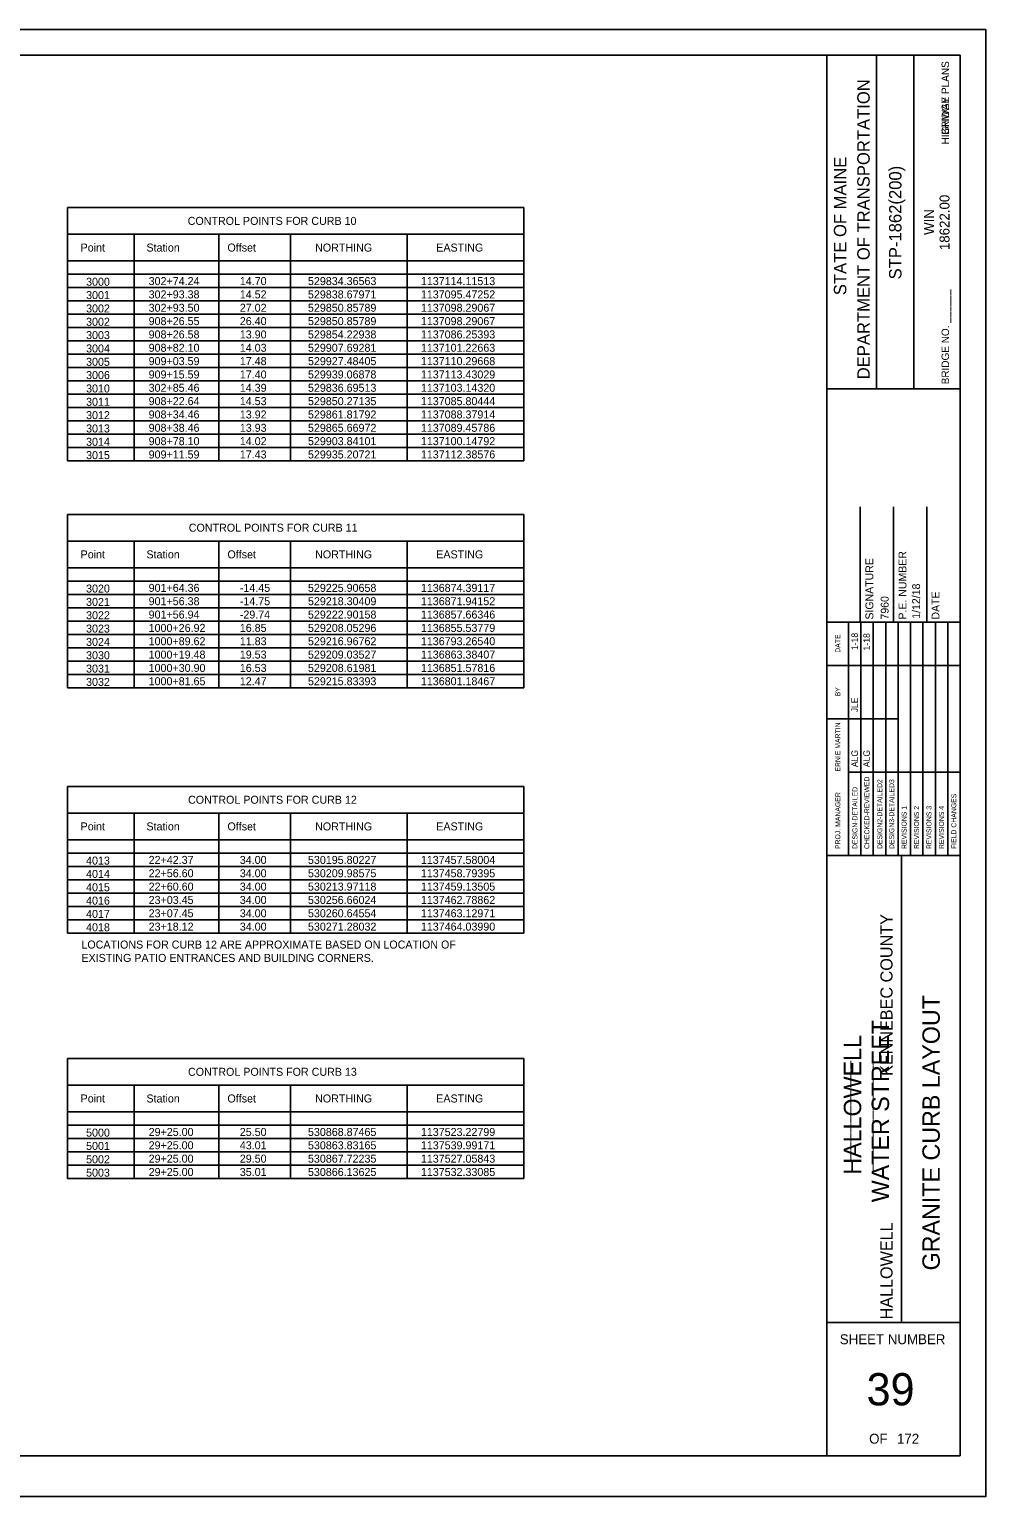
# Model space of a CAD drawing. Extents: x 0 to 850, y 0 to 550.
# Drawn here: x 491 to 850, y 0 to 550 of the extents above; entities that cross this region are included whole.
import ezdxf

# ---------------------------------------------------------------- set-up
doc = ezdxf.new("R2010")
doc.units = 0
for name, color, linetype in [('ANNOTATION', 7, 'Continuous'), ('BORDER', 7, 'Continuous'), ('BRIDGE_TITLE', 7, 'Continuous'), ('Default', 7, 'Continuous'), ('H_V CONTROLS', 7, 'Continuous'), ('HIGHWAY_TITLE', 7, 'Continuous'), ('PLOT BOUNDARY', 7, 'Continuous')]:
    doc.layers.add(name, color=color, linetype=linetype)

msp = doc.modelspace()

# ---------------------------------------------------------------- linework, layer by layer
at = {"layer": 'BORDER'}
for p, q in [((840.33, 540.24), (40.33, 540.24)), ((790.33, 15.26), (790.33, 540.26)), ((808.97, 415.23), (808.97, 540.23)), ((822.95, 415.23), (822.95, 540.23)), ((840.33, 15.26), (840.33, 540.26)), ((790.34, 415.22), (840.33, 415.22)), ((802.83, 327.76), (802.83, 371)), ((815.33, 327.76), (815.33, 371)), ((827.83, 327.76), (827.83, 371)), ((790.33, 327.76), (840.33, 327.76)), ((790.33, 240.26), (840.33, 240.26)), ((818.29, 65.26), (818.29, 240.26)), ((790.33, 65.26), (840.33, 65.26)), ((40.33, 15.24), (840.33, 15.24))]:
    msp.add_line(p, q, dxfattribs=at)
for points in [[(798.41, 311.51), (798.41, 327.76)], [(803.07, 240.27), (803.07, 327.76)], [(807.73, 327.76), (807.73, 240.27)], [(812.39, 240.27), (812.39, 327.76)], [(817.04, 240.27), (817.04, 327.76)], [(821.7, 240.27), (821.7, 327.76)], [(826.36, 240.27), (826.36, 327.76)], [(831.02, 240.27), (831.02, 327.76)], [(835.68, 240.27), (835.68, 327.76)], [(798.41, 240.27), (798.41, 324.23)], [(790.33, 311.51), (840.33, 311.51)], [(790.33, 291.51), (798.41, 291.51)], [(798.41, 291.51), (817.04, 291.51)], [(798.41, 271.51), (840.33, 271.51)]]:
    msp.add_lwpolyline(points, dxfattribs=at)
at = {"layer": 'Default'}
msp.add_lwpolyline([(40.33, 15.24), (790.33, 15.24), (790.33, 540.26), (40.33, 540.26)], close=True, dxfattribs=at)
at = {"layer": 'H_V CONTROLS'}
for p, q in [((505.47, 483.15), (676.71, 483.15)), ((505.47, 483.15), (505.47, 388.15)), ((676.71, 483.15), (676.71, 388.15)), ((505.47, 473.15), (676.71, 473.15)), ((530.51, 473.15), (530.51, 388.15)), ((562.29, 473.15), (562.29, 388.15)), ((589.21, 473.15), (589.21, 388.15)), ((632.96, 473.15), (632.96, 388.15)), ((505.47, 463.15), (676.71, 463.15)), ((505.47, 458.15), (676.71, 458.15)), ((505.47, 453.15), (676.71, 453.15)), ((505.47, 448.15), (676.71, 448.15)), ((505.47, 443.15), (676.71, 443.15)), ((505.47, 438.15), (676.71, 438.15)), ((505.47, 433.15), (676.71, 433.15)), ((505.47, 428.15), (676.71, 428.15)), ((505.47, 423.15), (676.71, 423.15)), ((505.47, 418.15), (676.71, 418.15)), ((505.47, 413.15), (676.71, 413.15)), ((505.47, 408.15), (676.71, 408.15)), ((505.47, 403.15), (676.71, 403.15)), ((505.47, 398.15), (676.71, 398.15)), ((505.47, 393.15), (676.71, 393.15)), ((505.47, 388.15), (676.71, 388.15)), ((505.47, 368.15), (676.71, 368.15)), ((505.47, 368.15), (505.47, 303.15)), ((676.71, 368.15), (676.71, 303.15)), ((505.47, 358.15), (676.71, 358.15)), ((530.51, 358.15), (530.51, 303.15)), ((562.29, 358.15), (562.29, 303.15)), ((589.21, 358.15), (589.21, 303.15)), ((632.96, 358.15), (632.96, 303.15)), ((505.47, 348.15), (676.71, 348.15)), ((505.47, 343.15), (676.71, 343.15)), ((505.47, 338.15), (676.71, 338.15)), ((505.47, 333.15), (676.71, 333.15)), ((505.47, 328.15), (676.71, 328.15)), ((505.47, 323.15), (676.71, 323.15)), ((505.47, 318.15), (676.71, 318.15)), ((505.47, 313.15), (676.71, 313.15)), ((505.47, 308.15), (676.71, 308.15)), ((505.47, 303.15), (676.71, 303.15)), ((505.47, 266.18), (676.71, 266.18)), ((505.47, 266.18), (505.47, 211.18)), ((676.71, 266.18), (676.71, 211.18)), ((505.47, 256.18), (676.71, 256.18)), ((530.51, 256.18), (530.51, 211.18)), ((562.29, 256.18), (562.29, 211.18)), ((589.21, 256.18), (589.21, 211.18)), ((632.96, 256.18), (632.96, 211.18)), ((505.47, 246.18), (676.71, 246.18)), ((505.47, 241.18), (676.71, 241.18)), ((505.47, 236.18), (676.71, 236.18)), ((505.47, 231.18), (676.71, 231.18)), ((505.47, 226.18), (676.71, 226.18)), ((505.47, 221.18), (676.71, 221.18)), ((505.47, 216.18), (676.71, 216.18)), ((505.47, 211.18), (676.71, 211.18)), ((505.47, 164.2), (676.71, 164.2)), ((505.47, 164.2), (505.47, 119.2)), ((676.71, 164.2), (676.71, 119.2)), ((505.47, 154.2), (676.71, 154.2)), ((530.51, 154.2), (530.51, 119.2)), ((562.29, 154.2), (562.29, 119.2)), ((589.21, 154.2), (589.21, 119.2)), ((632.96, 154.2), (632.96, 119.2)), ((505.47, 144.2), (676.71, 144.2)), ((505.47, 139.2), (676.71, 139.2)), ((505.47, 134.2), (676.71, 134.2)), ((505.47, 129.2), (676.71, 129.2)), ((505.47, 124.2), (676.71, 124.2)), ((505.47, 119.2), (676.71, 119.2))]:
    msp.add_line(p, q, dxfattribs=at)
at = {"layer": 'PLOT BOUNDARY'}
msp.add_lwpolyline([(-0.13, -0.05), (849.87, -0.05), (849.87, 549.95), (-0.13, 549.95)], close=True, dxfattribs=at)

# ---------------------------------------------------------------- texts
at = {"layer": 'ANNOTATION'}
for s, p in [('3000', (512.5, 453.84)), ('302+74.24', (535.96, 454.09)), ('14.70', (570.15, 454.09)), ('529834.36563', (595.71, 454.09)), ('1137114.11513', (638.05, 454.09)), ('3001', (512.5, 448.84)), ('302+93.38', (535.96, 449.09)), ('14.52', (570.15, 449.09)), ('529838.67971', (595.71, 449.09)), ('1137095.47252', (638.05, 449.09)), ('3002', (512.5, 443.84)), ('302+93.50', (535.96, 444.09)), ('27.02', (570.15, 444.09)), ('529850.85789', (595.71, 444.09)), ('1137098.29067', (638.05, 444.09)), ('3002', (512.5, 438.84)), ('908+26.55', (535.96, 439.09)), ('26.40', (570.15, 439.09)), ('529850.85789', (595.71, 439.09)), ('1137098.29067', (638.05, 439.09)), ('3003', (512.5, 433.84)), ('908+26.58', (535.96, 434.09)), ('13.90', (570.15, 434.09)), ('529854.22938', (595.71, 434.09)), ('1137086.25393', (638.05, 434.09)), ('3004', (512.5, 428.84)), ('908+82.10', (535.96, 429.09)), ('14.03', (570.15, 429.09)), ('529907.69281', (595.71, 429.09)), ('1137101.22663', (638.05, 429.09)), ('3005', (512.5, 423.84)), ('909+03.59', (535.96, 424.09)), ('17.48', (570.15, 424.09)), ('529927.48405', (595.71, 424.09)), ('1137110.29668', (638.05, 424.09)), ('3006', (512.5, 418.84)), ('909+15.59', (535.96, 419.09)), ('17.40', (570.15, 419.09)), ('529939.06878', (595.71, 419.09)), ('1137113.43029', (638.05, 419.09)), ('3010', (512.5, 413.84)), ('302+85.46', (535.96, 414.09)), ('14.39', (570.15, 414.09)), ('529836.69513', (595.71, 414.09)), ('1137103.14320', (638.05, 414.09)), ('3011', (512.5, 408.84)), ('908+22.64', (535.96, 409.09)), ('908+34.46', (535.96, 404.09)), ('14.53', (570.15, 409.09)), ('13.92', (570.15, 404.09)), ('529850.27135', (595.71, 409.09)), ('529861.81792', (595.71, 404.09)), ('1137085.80444', (638.05, 409.09)), ('1137088.37914', (638.05, 404.09)), ('3012', (512.5, 403.84)), ('3013', (512.5, 398.85)), ('908+38.46', (535.96, 399.09)), ('13.93', (570.15, 399.09)), ('529865.66972', (595.71, 399.09)), ('1137089.45786', (638.05, 399.09)), ('3014', (512.5, 393.85)), ('908+78.10', (535.96, 394.09)), ('14.02', (570.15, 394.09)), ('529903.84101', (595.71, 394.09)), ('1137100.14792', (638.05, 394.09)), ('3015', (512.5, 388.85)), ('909+11.59', (535.96, 389.1)), ('17.43', (570.15, 389.1)), ('529935.20721', (595.71, 389.1)), ('1137112.38576', (638.05, 389.1)), ('3020', (512.5, 338.84)), ('901+64.36', (535.96, 339.09)), ('-14.45', (570.15, 339.09)), ('529225.90658', (595.71, 339.09)), ('1136874.39117', (638.05, 339.09)), ('3021', (512.5, 333.84)), ('901+56.38', (535.96, 334.09)), ('-14.75', (570.15, 334.09)), ('529218.30409', (595.71, 334.09)), ('1136871.94152', (638.05, 334.09)), ('3022', (512.5, 328.84)), ('901+56.94', (535.96, 329.09)), ('-29.74', (570.15, 329.09)), ('529222.90158', (595.71, 329.09)), ('1136857.66346', (638.05, 329.09)), ('3023', (512.5, 323.84)), ('1000+26.92', (535.96, 324.09)), ('16.85', (570.15, 324.09)), ('529208.05296', (595.71, 324.09)), ('1136855.53779', (638.05, 324.09)), ('3024', (512.5, 318.84)), ('1000+89.62', (535.96, 319.09)), ('11.83', (570.15, 319.09)), ('529216.96762', (595.71, 319.09)), ('1136793.26540', (638.05, 319.09)), ('3030', (512.5, 313.84)), ('1000+19.48', (535.96, 314.09)), ('19.53', (570.15, 314.09)), ('529209.03527', (595.71, 314.09)), ('1136863.38407', (638.05, 314.09)), ('3031', (512.5, 308.84)), ('1000+30.90', (535.96, 309.09)), ('16.53', (570.15, 309.09)), ('529208.61981', (595.71, 309.09)), ('1136851.57816', (638.05, 309.09)), ('3032', (512.5, 303.84)), ('1000+81.65', (535.96, 304.09)), ('12.47', (570.15, 304.09)), ('529215.83393', (595.71, 304.09)), ('1136801.18467', (638.05, 304.09)), ('4013', (512.5, 236.87)), ('22+42.37', (535.96, 237.12)), ('34.00', (570.15, 237.12)), ('530195.80227', (595.71, 237.12)), ('1137457.58004', (638.05, 237.12)), ('4014', (512.5, 231.87)), ('22+56.60', (535.96, 232.12)), ('34.00', (570.15, 232.12)), ('530209.98575', (595.71, 232.12)), ('1137458.79395', (638.05, 232.12)), ('4015', (512.5, 226.87)), ('22+60.60', (535.96, 227.12)), ('34.00', (570.15, 227.12)), ('530213.97118', (595.71, 227.12)), ('1137459.13505', (638.05, 227.12)), ('4016', (512.5, 221.87)), ('23+03.45', (535.96, 222.12)), ('23+07.45', (535.96, 217.12)), ('34.00', (570.15, 222.12)), ('34.00', (570.15, 217.12)), ('530256.66024', (595.71, 222.12)), ('530260.64554', (595.71, 217.12)), ('1137462.78862', (638.05, 222.12)), ('1137463.12971', (638.05, 217.12)), ('4017', (512.5, 216.87)), ('4018', (512.5, 211.87)), ('23+18.12', (535.96, 212.12)), ('34.00', (570.15, 212.12)), ('530271.28032', (595.71, 212.12)), ('1137464.03990', (638.05, 212.12)), ('LOCATIONS FOR CURB 12 ARE APPROXIMATE BASED ON LOCATION OF ', (510.74, 205.39)), ('EXISTING PATIO ENTRANCES AND BUILDING CORNERS.', (510.74, 200.39)), ('5000', (512.5, 134.9)), ('29+25.00', (535.96, 135.15)), ('25.50', (570.15, 135.15)), ('530868.87465', (595.71, 135.15)), ('1137523.22799', (638.05, 135.15)), ('5001', (512.5, 129.9)), ('29+25.00', (535.96, 130.15)), ('43.01', (570.15, 130.15)), ('530863.83165', (595.71, 130.15)), ('1137539.99171', (638.05, 130.15)), ('5002', (512.5, 124.9)), ('29+25.00', (535.96, 125.15)), ('29.50', (570.15, 125.15)), ('530867.72235', (595.71, 125.15)), ('1137527.05843', (638.05, 125.15)), ('5003', (512.5, 119.9)), ('29+25.00', (535.96, 120.15)), ('35.01', (570.15, 120.15)), ('530866.13625', (595.71, 120.15)), ('1137532.33085', (638.05, 120.15))]:
    msp.add_text(s, height=3, rotation=360, dxfattribs=at).set_placement(p)
at = {"layer": 'BORDER'}
for s, height, p in [('DEPARTMENT OF TRANSPORTATION', 4.6588, (806.37, 418.77)), ('STATE OF MAINE', 4.6588, (797.61, 450.3)), ('STP-1862(200)', 4.6588, (818.29, 456.21)), ('18622.00', 3.726, (836.31, 467.18)), ('WIN', 3.726, (830.52, 472.89)), ('P.E. NUMBER', 2.9528, (820.14, 328.72)), ('SIGNATURE', 2.953, (807.73, 328.72)), ('1/12/18', 2.953, (825.27, 329.02)), ('7960', 2.953, (813.47, 328.72)), ('DATE', 2.953, (832.54, 328.72)), ('DATE', 1.857, (795.35, 316.29)), ('1-18', 2.423, (801.95, 317.25)), ('1-18', 2.423, (806.42, 317.14)), ('BY', 1.857, (795.35, 299.93)), ('JLE', 2.423, (801.95, 293.93)), ('ERNIE MARTIN', 1.8637, (795.35, 271.72)), ('ALG', 2.423, (801.95, 273.38)), ('ALG', 2.423, (806.42, 273.38)), ('DESIGN-DETAILED', 1.8637, (801.76, 242.7)), ('CHECKED-REVIEWED', 1.8637, (806.24, 242.7)), ('DESIGN2-DETAILED2', 1.8637, (811.08, 242.7)), ('DESIGN3-DETAILED3', 1.8637, (815.55, 242.7)), ('PROJ. MANAGER', 1.8637, (795.35, 242.7)), ('FIELD CHANGES', 1.8637, (838.85, 242.7)), ('REVISIONS 1', 1.8637, (820.21, 242.7)), ('REVISIONS 2', 1.8637, (824.87, 242.7)), ('REVISIONS 3', 1.8637, (829.53, 242.7)), ('REVISIONS 4', 1.8637, (834.19, 242.7)), ('GRANITE CURB LAYOUT', 6.5214, (832.66, 84.75))]:
    msp.add_text(s, height=height, rotation=90, dxfattribs=at).set_placement(p)
for s, height, p in [('SHEET NUMBER', 3.7264, (795.16, 57.08)), ('39', 12.097, (805.21, 34.16)), ('OF', 3.726, (806.17, 19.81)), ('172', 3.726, (816.61, 19.81))]:
    msp.add_text(s, height=height, dxfattribs=at).set_placement(p)
at = {"layer": 'BRIDGE_TITLE'}
for s, height, p in [('BRIDGE PLANS', 2.795, (836.12, 510.37)), ('BRIDGE NO. ______', 2.795, (836.12, 416.9)), ('KENNEBEC COUNTY', 4.5358, (814.93, 157.65)), ('_____________', 4.5358, (806.55, 121.2)), ('___________', 4.5358, (798.16, 126.17)), ('HALLOWELL', 4.536, (814.93, 66.36))]:
    msp.add_text(s, height=height, rotation=90, dxfattribs=at).set_placement(p)
at = {"layer": 'H_V CONTROLS'}
for s, p in [('CONTROL POINTS FOR CURB 10', (550.6, 476.65)), ('Point', (510.44, 466.65)), ('Station', (535.14, 466.65)), ('Offset', (565.51, 466.65)), ('NORTHING', (598.38, 466.65)), ('EASTING', (643.83, 466.65)), ('CONTROL POINTS FOR CURB 11', (551.01, 361.65)), ('Point', (510.44, 351.65)), ('Station', (535.14, 351.65)), ('Offset', (565.51, 351.65)), ('NORTHING', (598.38, 351.65)), ('EASTING', (643.83, 351.65)), ('CONTROL POINTS FOR CURB 12', (550.73, 259.68)), ('Point', (510.44, 249.68)), ('Station', (535.14, 249.68)), ('Offset', (565.51, 249.68)), ('NORTHING', (598.38, 249.68)), ('EASTING', (643.83, 249.68)), ('CONTROL POINTS FOR CURB 13', (550.73, 157.7)), ('Point', (510.44, 147.7)), ('Station', (535.14, 147.7)), ('Offset', (565.51, 147.7)), ('NORTHING', (598.38, 147.7)), ('EASTING', (643.83, 147.7))]:
    msp.add_text(s, height=3, rotation=360, dxfattribs=at).set_placement(p)
at = {"layer": 'HIGHWAY_TITLE'}
for s, height, p in [('HIGHWAY PLANS', 2.795, (836.12, 506.82)), ('WATER STREET', 6.5214, (813.63, 110.3)), ('HALLOWELL', 6.521, (803.19, 120.63))]:
    msp.add_text(s, height=height, rotation=90, dxfattribs=at).set_placement(p)

doc.saveas('drawing.dxf')
